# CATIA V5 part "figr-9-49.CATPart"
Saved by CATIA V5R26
Part number: Part1
Bounding box of the stored display mesh (mm): x -53.48 to 62.241, y -50 to 50, z -57.709 to 133.109
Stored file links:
  D:\_Deepak\CATIA\CATIA V5-6R2016_Deepak\Resources\Part files\Partfiles\c09_catia_v5_6r2016_prt\figr-9-49.CATPart
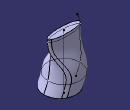
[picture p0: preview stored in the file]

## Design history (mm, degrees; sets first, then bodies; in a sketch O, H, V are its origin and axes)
Body1 (main body)
  Plane1: type Offset, RefPlane xy-plane, Offset 103
  Sketch1 on Plane1, origin (0, 0, 103), H (1, 0, 0), V (0, 1, 0)
    ellipse A1 centre (0, 0) semi-axes 50, 13.2069 rotation 0
    point P1 (50, 0)
    "Radius" A1 = 50
    coincidence: P1 H, A1 P1
  Extremum1: Reference Sketch1, Direction (1, 2, 3)
  Sketch2 on xy-plane, origin (0, 0, 0), H (1, 0, 0), V (0, 1, 0)
    circle A1 centre (0, 0) radius 50
    radius A1 = 50
  Extremum2: Reference Sketch2, Direction (1, 2, 3)
  Sketch3 on zx-plane, origin (0, 0, 0), H (-1, 0, 0), V (0, 0, 1)
    spline S1 through (37.7591, -31.0289) (41.8235, -21.251) (50, 0) (49.8084, 85.7657) (50, 103) (41.6255, 133.1089)
    reference projected line E1 (-50, 103) -> (50, 103) from Sketch1.A1
    point P1 (50, 0)
    point P2 (50, 103)
    distance V P1 = 50
    distance P2 V = 50
    coincidence: P1 H, P2 E1
  Sketch4 on zx-plane, origin (0, 0, 0), H (-1, 0, 0), V (0, 0, 1)
    line L1 (0, 111.062) -> (0, -57.7094)
    point P1 (0, 111.062)
    coincidence: P1 V
    vertical: L1 V
  Loft1: solid, Sections (Sketch1; Sketch2), Spine Sketch4, Guides Sketch3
